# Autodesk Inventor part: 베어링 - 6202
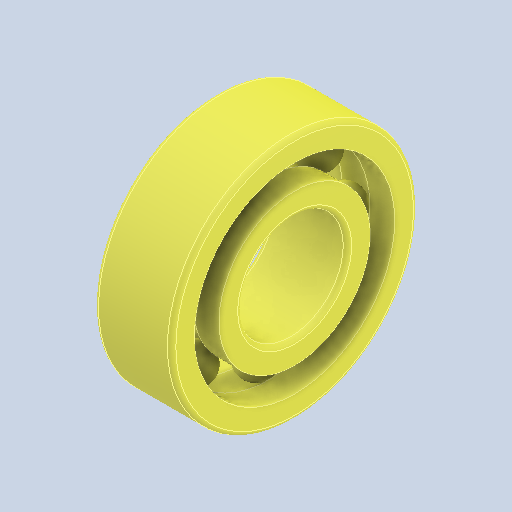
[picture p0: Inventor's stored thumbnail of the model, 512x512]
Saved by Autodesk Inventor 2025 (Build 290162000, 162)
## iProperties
Created: 2024-07
Part Number: 베어링 - 6202
Material: 강, 연강
Description: 깊은 그루브 볼 베어링
Document SubType Name: Modeling
Designer: onair
Density: 7.86 g/cm^3
Appearance: 기본값
Author: jhkim
Sending System: Autodesk Inventor 2025
Preprocessor: ST-DEVELOPER v20
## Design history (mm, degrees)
feature "Solid1"
feature "Solid1:1"
feature "Solid1:2"
feature "Solid1:3"
feature "Solid1:4"
feature "Solid1:5"
feature "Solid1:6"
feature "Solid1:7"
feature "Solid1:8"
feature "Solid1:9"
node "솔리드1"
node "솔리드2"
node "솔리드3"
node "솔리드4"
node "솔리드5"
node "솔리드6"
node "솔리드7"
node "솔리드8"
node "솔리드9"
node "솔리드10"
